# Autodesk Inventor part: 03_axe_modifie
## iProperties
Created: 2002-11
Part Number: 03_axe_modifie
Material: Acier doux
Document SubType Name: Modélisation
Designer: poste-2
Control State: 0
Master: False
Checked Out: False
Shininess: 31.0
Length Units: 11269
Angle Units: 11279
Time Units: 11290
Mass Units: 11283
Length Display Precision: 3
Angle Display Precision: 2
Compacted: True
Density: 7.86
Volumn: 1.677510786885382
Area: 10.323396518310158
PropertySet Name: Model Information
Author: poste-2
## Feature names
1. Révolution1 [Revolution]
2. Extrusion1
3. Extrusion3
4. Congé1 [Fillet]
